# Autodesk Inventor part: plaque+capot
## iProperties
Created: 2009-01
Part Number: plaque+capot
Document SubType Name: Modeling
Designer: LECHENAULT
Author: LECHENAULT
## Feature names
1. Extrusion1
2. Extrusion2
3. Extrusion3
4. Extrusion4
